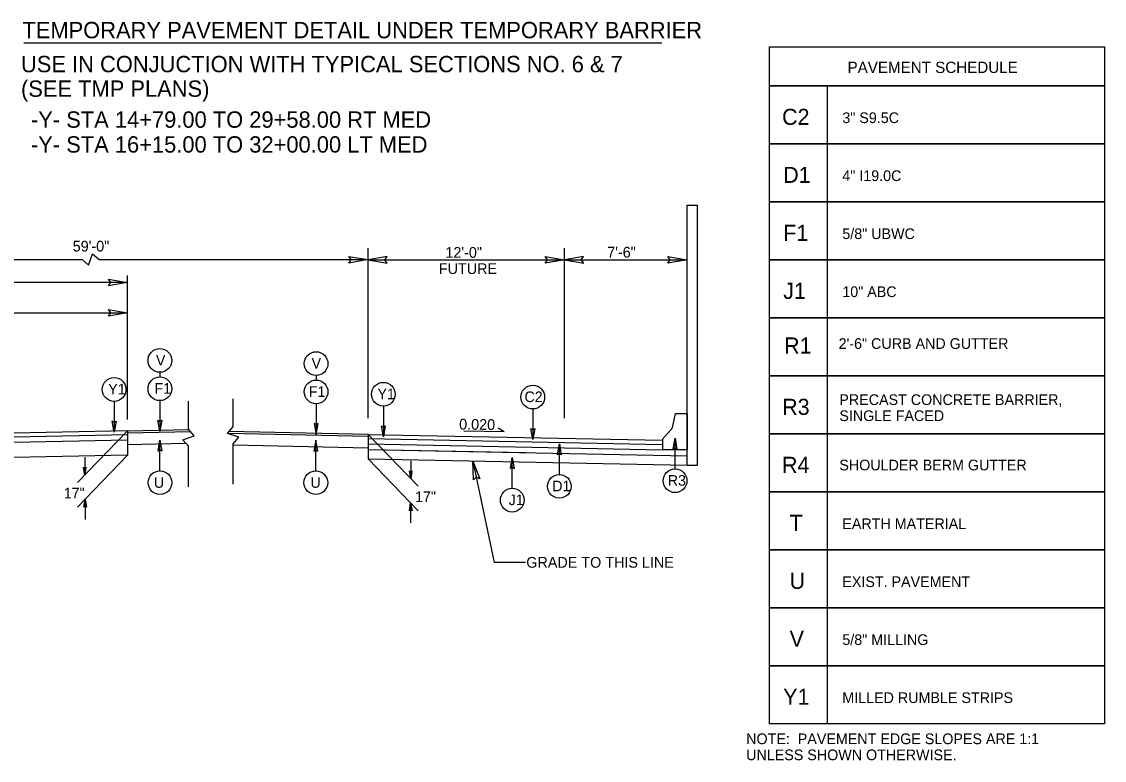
# Model space of a CAD drawing. Extents: x 1901582 to 1902252, y 193723 to 194156.
# Drawn here: x 1902064.9 to 1902131, y 193832.2 to 193877.4 of the extents above; entities that cross this region are included whole.
import ezdxf

# ---------------------------------------------------------------- set-up
doc = ezdxf.new("R2010")
doc.units = 0
for name, color, linetype in [('Old_Level_1', 7, 'Continuous'), ('Old_Level_11', 7, 'Continuous'), ('Old_Level_2', 7, 'Continuous'), ('Old_Level_20', 7, 'Continuous'), ('Old_Level_21', 7, 'Continuous'), ('Prop Dimension', 7, 'Continuous'), ('Prop Dimension Text', 7, 'Continuous'), ('Prop Pavement Schedule Description CELL', 7, 'Continuous'), ('Prop Roadway Bridge', 7, 'Continuous'), ('Typical Bridge Rail CELL', 7, 'Continuous'), ('Typical Pavement Slope Information CELL', 7, 'Continuous'), ('Typical Terminator CELL', 7, 'Continuous'), ('Typical Text Asphalt at Bridge Approach CELL', 7, 'Continuous')]:
    doc.layers.add(name, color=color, linetype=linetype)

msp = doc.modelspace()

# ---------------------------------------------------------------- linework, layer by layer
at = {"layer": 'Old_Level_1'}
for p, q in [((1902071.36, 193852.371), (1902052.61, 193851.996)), ((1902071.36, 193852.371), (1902068.292, 193849.202)), ((1902071.36, 193852.371), (1902075.103, 193852.446)), ((1902071.36, 193852.371), (1902071.36, 193850.871)), ((1902071.36, 193852.245), (1902075.209, 193852.322)), ((1902086.05, 193852.15), (1902077.548, 193852.32)), ((1902086.05, 193852.15), (1902077.548, 193852.32)), ((1902071.36, 193851.788), (1902048.36, 193851.328)), ((1902071.36, 193852.121), (1902052.61, 193851.746)), ((1902071.36, 193851.538), (1902074.918, 193851.609)), ((1902086.05, 193852.024), (1902077.504, 193852.195)), ((1902086.05, 193852.15), (1902104.05, 193851.79)), ((1902086.05, 193852.15), (1902086.05, 193850.65)), ((1902086.05, 193852.15), (1902089.118, 193848.98)), ((1902086.05, 193851.317), (1902077.81, 193851.481)), ((1902086.05, 193851.233), (1902095.693, 193851.04)), ((1902086.05, 193851.233), (1902105.55, 193850.843)), ((1902071.36, 193850.871), (1902048.36, 193850.411)), ((1902071.36, 193850.871), (1902068.292, 193847.701)), ((1902068.741, 193850.754), (1902068.741, 193849.665)), ((1902086.05, 193850.65), (1902089.118, 193847.48)), ((1902086.05, 193850.65), (1902105.55, 193850.26)), ((1902088.669, 193850.532), (1902088.669, 193849.444)), ((1902092.458, 193850.522), (1902093.755, 193844.323)), ((1902068.741, 193849.665), (1902068.657, 193850.142)), ((1902068.741, 193849.665), (1902068.669, 193850.133)), ((1902068.681, 193850.124), (1902068.741, 193849.665)), ((1902068.741, 193849.665), (1902068.693, 193850.116)), ((1902068.705, 193850.107), (1902068.741, 193849.665)), ((1902068.741, 193849.665), (1902068.717, 193850.098)), ((1902068.729, 193850.089), (1902068.741, 193849.665)), ((1902068.741, 193849.665), (1902068.826, 193850.142)), ((1902068.814, 193850.133), (1902068.741, 193849.665)), ((1902068.741, 193849.665), (1902068.801, 193850.124)), ((1902068.789, 193850.116), (1902068.741, 193849.665)), ((1902068.741, 193849.665), (1902068.777, 193850.107)), ((1902068.765, 193850.098), (1902068.741, 193849.665)), ((1902068.741, 193849.665), (1902068.753, 193850.089)), ((1902068.741, 193850.08), (1902068.741, 193849.665)), ((1902088.669, 193849.444), (1902088.585, 193849.921)), ((1902088.596, 193849.912), (1902088.669, 193849.444)), ((1902088.669, 193849.444), (1902088.61, 193849.903)), ((1902088.622, 193849.895), (1902088.669, 193849.444)), ((1902088.669, 193849.444), (1902088.634, 193849.886)), ((1902088.645, 193849.877), (1902088.669, 193849.444)), ((1902088.669, 193849.444), (1902088.657, 193849.868)), ((1902088.669, 193849.444), (1902088.753, 193849.921)), ((1902088.669, 193849.444), (1902088.742, 193849.912)), ((1902088.73, 193849.903), (1902088.669, 193849.444)), ((1902088.669, 193849.444), (1902088.718, 193849.895)), ((1902088.705, 193849.886), (1902088.669, 193849.444)), ((1902088.669, 193849.444), (1902088.693, 193849.877)), ((1902088.681, 193849.868), (1902088.669, 193849.444)), ((1902088.669, 193849.859), (1902088.669, 193849.444)), ((1902068.758, 193848.182), (1902068.673, 193847.705)), ((1902068.685, 193847.714), (1902068.758, 193848.182)), ((1902068.758, 193848.182), (1902068.697, 193847.723)), ((1902068.709, 193847.732), (1902068.758, 193848.182)), ((1902068.758, 193848.182), (1902068.722, 193847.741)), ((1902068.734, 193847.749), (1902068.758, 193848.182)), ((1902068.758, 193848.182), (1902068.746, 193847.758)), ((1902068.758, 193848.182), (1902068.842, 193847.705)), ((1902068.769, 193847.758), (1902068.758, 193848.182)), ((1902068.758, 193848.182), (1902068.781, 193847.749)), ((1902068.793, 193847.741), (1902068.758, 193848.182)), ((1902068.758, 193848.182), (1902068.805, 193847.732)), ((1902068.817, 193847.723), (1902068.758, 193848.182)), ((1902068.758, 193848.182), (1902068.83, 193847.714)), ((1902068.758, 193848.182), (1902068.758, 193846.957)), ((1902088.653, 193847.961), (1902088.568, 193847.484)), ((1902088.653, 193847.961), (1902088.58, 193847.493)), ((1902088.593, 193847.502), (1902088.653, 193847.961)), ((1902088.653, 193847.961), (1902088.605, 193847.511)), ((1902088.617, 193847.519), (1902088.653, 193847.961)), ((1902088.653, 193847.961), (1902088.629, 193847.528)), ((1902088.641, 193847.537), (1902088.653, 193847.961)), ((1902088.653, 193847.961), (1902088.737, 193847.484)), ((1902088.725, 193847.493), (1902088.653, 193847.961)), ((1902088.653, 193847.961), (1902088.713, 193847.502)), ((1902088.701, 193847.511), (1902088.653, 193847.961)), ((1902088.653, 193847.961), (1902088.689, 193847.519)), ((1902088.677, 193847.528), (1902088.653, 193847.961)), ((1902088.653, 193847.961), (1902088.665, 193847.537)), ((1902088.653, 193847.961), (1902088.653, 193846.736)), ((1902095.664, 193844.323), (1902093.755, 193844.323))]:
    msp.add_line(p, q, dxfattribs=at)
at = {"layer": 'Old_Level_11'}
for p, q in [((1902065.016, 193876.08), (1902104.001, 193876.08)), ((1902073.331, 193855.942), (1902073.331, 193855.664)), ((1902082.874, 193855.749), (1902082.874, 193855.471)), ((1902073.331, 193854.213), (1902073.331, 193852.339)), ((1902070.533, 193854.169), (1902070.533, 193852.295)), ((1902082.874, 193854.02), (1902082.874, 193852.146)), ((1902086.987, 193853.877), (1902086.987, 193852.003)), ((1902096.117, 193853.704), (1902096.117, 193851.83)), ((1902073.334, 193849.925), (1902073.334, 193851.8)), ((1902082.859, 193849.923), (1902082.859, 193851.797)), ((1902097.742, 193849.701), (1902097.742, 193851.575)), ((1902104.812, 193850.043), (1902104.812, 193851.917)), ((1902094.864, 193848.856), (1902094.864, 193850.73))]:
    msp.add_line(p, q, dxfattribs=at)
for points in [[(1902070.648, 193852.966), (1902070.533, 193852.295), (1902070.413, 193852.97), (1902070.533, 193852.884)], [(1902073.446, 193853.011), (1902073.331, 193852.339), (1902073.211, 193853.014), (1902073.331, 193852.928)], [(1902082.759, 193852.818), (1902082.874, 193852.146), (1902082.994, 193852.821), (1902082.874, 193852.735)], [(1902087.103, 193852.674), (1902086.987, 193852.003), (1902086.868, 193852.678), (1902086.987, 193852.592)], [(1902096.233, 193852.502), (1902096.117, 193851.83), (1902095.998, 193852.505), (1902096.117, 193852.42)], [(1902073.218, 193851.128), (1902073.334, 193851.8), (1902073.453, 193851.124), (1902073.334, 193851.21)], [(1902082.975, 193851.126), (1902082.859, 193851.797), (1902082.74, 193851.122), (1902082.859, 193851.208)], [(1902097.626, 193850.903), (1902097.742, 193851.575), (1902097.861, 193850.9), (1902097.742, 193850.985)], [(1902104.696, 193851.246), (1902104.812, 193851.917), (1902104.931, 193851.242), (1902104.812, 193851.328)], [(1902094.749, 193850.059), (1902094.864, 193850.73), (1902094.984, 193850.055), (1902094.864, 193850.141)]]:
    msp.add_lwpolyline(points, close=True, dxfattribs=at)
for centre in [(1902073.331, 193856.667), (1902082.874, 193856.474), (1902070.533, 193854.894), (1902073.331, 193854.938), (1902082.874, 193854.745), (1902086.987, 193854.602), (1902096.117, 193854.43), (1902073.334, 193849.2), (1902082.859, 193849.198), (1902097.742, 193848.976), (1902104.812, 193849.318), (1902094.864, 193848.131)]:
    msp.add_circle(centre, 0.725, dxfattribs=at)
at = {"layer": 'Prop Dimension'}
for p, q in [((1902086.05, 193853.142), (1902086.05, 193863.53)), ((1902098.05, 193853.142), (1902098.05, 193863.53)), ((1902086.05, 193862.825), (1902098.05, 193862.825)), ((1902098.05, 193862.825), (1902105.55, 193862.825)), ((1902071.36, 193853.064), (1902071.36, 193861.864)), ((1902071.36, 193861.432), (1902025.36, 193861.432)), ((1902051.11, 193859.581), (1902071.36, 193859.581)), ((1902086.05, 193851.9), (1902104.05, 193851.54)), ((1902086.05, 193851.567), (1902104.05, 193851.207))]:
    msp.add_line(p, q, dxfattribs=at)
msp.add_lwpolyline([(1902048.36, 193862.826), (1902068.573, 193862.826), (1902068.97, 193862.485), (1902069.212, 193863.182), (1902069.625, 193862.827), (1902086.05, 193862.826)], dxfattribs=at)
at = {"layer": 'Prop Pavement Schedule Description CELL'}
msp.add_lwpolyline([(1902110.585, 193875.841), (1902131.047, 193875.841), (1902131.047, 193873.438), (1902110.585, 193873.438)], close=True, dxfattribs=at)
for points in [[(1902114.129, 193869.894), (1902110.585, 193869.894), (1902110.585, 193873.438), (1902131.047, 193873.438), (1902131.047, 193869.894), (1902114.129, 193869.894), (1902114.129, 193873.438)], [(1902114.129, 193866.351), (1902110.585, 193866.351), (1902110.585, 193869.894), (1902131.047, 193869.894), (1902131.047, 193866.351), (1902114.129, 193866.351), (1902114.129, 193869.894)], [(1902114.129, 193862.807), (1902110.585, 193862.807), (1902110.585, 193866.351), (1902131.047, 193866.351), (1902131.047, 193862.807), (1902114.129, 193862.807), (1902114.129, 193866.351)], [(1902114.129, 193859.263), (1902110.585, 193859.263), (1902110.585, 193862.807), (1902131.047, 193862.807), (1902131.047, 193859.263), (1902114.129, 193859.263), (1902114.129, 193862.807)], [(1902114.129, 193855.72), (1902110.585, 193855.72), (1902110.585, 193859.263), (1902131.047, 193859.263), (1902131.047, 193855.72), (1902114.129, 193855.72), (1902114.129, 193859.263)], [(1902114.129, 193852.176), (1902110.585, 193852.176), (1902110.585, 193855.72), (1902131.047, 193855.72), (1902131.047, 193852.176), (1902114.129, 193852.176), (1902114.129, 193855.72)], [(1902114.129, 193848.632), (1902110.585, 193848.632), (1902110.585, 193852.176), (1902131.047, 193852.176), (1902131.047, 193848.632), (1902114.129, 193848.632), (1902114.129, 193852.176)], [(1902114.129, 193845.089), (1902110.585, 193845.089), (1902110.585, 193848.632), (1902131.047, 193848.632), (1902131.047, 193845.089), (1902114.129, 193845.089), (1902114.129, 193848.632)], [(1902114.129, 193841.545), (1902110.585, 193841.545), (1902110.585, 193845.089), (1902131.047, 193845.089), (1902131.047, 193841.545), (1902114.129, 193841.545), (1902114.129, 193845.089)], [(1902114.129, 193838.001), (1902110.585, 193838.001), (1902110.585, 193841.545), (1902131.047, 193841.545), (1902131.047, 193838.001), (1902114.129, 193838.001), (1902114.129, 193841.545)], [(1902114.129, 193834.458), (1902110.585, 193834.458), (1902110.585, 193838.001), (1902131.047, 193838.001), (1902131.047, 193834.458), (1902114.129, 193834.458), (1902114.129, 193838.001)]]:
    msp.add_lwpolyline(points, dxfattribs=at)
at = {"layer": 'Prop Roadway Bridge'}
for p, q in [((1902105.55, 193850.26), (1902105.55, 193866.153)), ((1902105.55, 193866.153), (1902106.19, 193866.153)), ((1902106.19, 193850.26), (1902106.19, 193866.153)), ((1902105.55, 193850.26), (1902106.19, 193850.26))]:
    msp.add_line(p, q, dxfattribs=at)
at = {"layer": 'Typical Bridge Rail CELL'}
for p, q in [((1902104.681, 193852.657), (1902104.846, 193853.431)), ((1902104.846, 193853.431), (1902105.524, 193853.431)), ((1902105.524, 193853.431), (1902105.55, 193853.405)), ((1902105.55, 193853.405), (1902105.55, 193851.206)), ((1902104.05, 193851.859), (1902104.563, 193852.426)), ((1902104.05, 193851.859), (1902104.05, 193851.206)), ((1902105.55, 193851.206), (1902104.05, 193851.207))]:
    msp.add_line(p, q, dxfattribs=at)
msp.add_arc((1902104.192, 193852.761), 0.5, 317.86989, 348.00424, dxfattribs=at)
at = {"layer": 'Typical Pavement Slope Information CELL'}
for q in [(1902091.901, 193852.352), (1902093.995, 193852.529)]:
    msp.add_line((1902094.371, 193852.302), q, dxfattribs=at)
at = {"layer": 'Typical Terminator CELL'}
for points in [[(1902084.878, 193863.028), (1902086.05, 193862.826), (1902084.872, 193862.618), (1902085.021, 193862.826)], [(1902087.222, 193863.027), (1902086.05, 193862.825), (1902087.228, 193862.617), (1902087.078, 193862.825)], [(1902096.878, 193863.027), (1902098.05, 193862.825), (1902096.872, 193862.617), (1902097.021, 193862.825)], [(1902099.222, 193863.027), (1902098.05, 193862.825), (1902099.228, 193862.617), (1902099.078, 193862.825)], [(1902104.378, 193863.027), (1902105.55, 193862.825), (1902104.372, 193862.617), (1902104.521, 193862.825)], [(1902070.188, 193861.634), (1902071.36, 193861.432), (1902070.182, 193861.224), (1902070.332, 193861.432)], [(1902070.188, 193859.783), (1902071.36, 193859.581), (1902070.182, 193859.373), (1902070.332, 193859.581)], [(1902092.5, 193849.366), (1902092.458, 193850.522), (1902092.892, 193849.441), (1902092.663, 193849.542)]]:
    msp.add_lwpolyline(points, close=True, dxfattribs=at)
at = {"layer": 'Typical Text Asphalt at Bridge Approach CELL'}
for points in [[(1902077.81, 193849.098), (1902077.81, 193851.573), (1902078.152, 193851.97), (1902077.455, 193852.212), (1902077.81, 193852.625), (1902077.814, 193854.327)], [(1902075.079, 193848.947), (1902075.079, 193851.422), (1902074.737, 193851.819), (1902075.433, 193852.061), (1902075.079, 193852.474), (1902075.075, 193854.176)]]:
    msp.add_lwpolyline(points, dxfattribs=at)

# ---------------------------------------------------------------- texts
at = {"layer": 'Old_Level_1'}
for s, p in [('59\'-0"', (1902068.002, 193863.322)), ('12\'-0"', (1902090.778, 193862.939)), ('7\'-6"', (1902100.666, 193862.955)), ('GRADE TO THIS LINE', (1902095.722, 193844.003))]:
    msp.add_text(s, height=0.656, dxfattribs=at).set_placement(p)
at = {"layer": 'Old_Level_11'}
for s, p in [('TEMPORARY PAVEMENT DETAIL UNDER TEMPORARY BARRIER', (1902064.93, 193876.354)), ('USE IN CONJUCTION WITH TYPICAL SECTIONS NO. 6 & 7', (1902064.841, 193874.277)), ('(SEE TMP PLANS)', (1902064.841, 193872.777)), ('-Y- STA 14+79.00 TO 29+58.00 RT MED', (1902065.45, 193870.887)), ('-Y- STA 16+15.00 TO 32+00.00 LT MED', (1902065.45, 193869.367))]:
    msp.add_text(s, height=1, dxfattribs=at).set_placement(p)
at = {"layer": 'Old_Level_2'}
msp.add_text('0.020', height=0.656, rotation=359.20147, dxfattribs=at).set_placement((1902091.615, 193852.448))
at = {"layer": 'Old_Level_20'}
for s, height, p in [('V', 0.649, (1902073.088, 193856.361)), ('V', 0.649, (1902082.601, 193856.168)), ('Y1', 0.6491, (1902070.172, 193854.588)), ('F1', 0.6491, (1902072.999, 193854.632)), ('F1', 0.6491, (1902082.433, 193854.439)), ('Y1', 0.6491, (1902086.627, 193854.296)), ('C2', 0.6491, (1902095.611, 193854.123)), ('R3', 0.6491, (1902104.367, 193849.014)), ('U', 0.649, (1902072.962, 193848.886)), ('U', 0.649, (1902082.531, 193848.883)), ('D1', 0.6491, (1902097.309, 193848.672)), ('17"', 0.6491, (1902067.455, 193848.24)), ('17"', 0.6491, (1902088.926, 193848.018)), ('J1', 0.6491, (1902094.646, 193847.827))]:
    msp.add_text(s, height=height, dxfattribs=at).set_placement(p)
at = {"layer": 'Old_Level_21'}
for s, height, p in [('C2', 0.98, (1902111.353, 193871.062)), ('3" S9.5C', 0.653, (1902115.034, 193871.172)), ('D1', 0.98, (1902111.423, 193867.518)), ('4" I19.0C', 0.653, (1902115.034, 193867.629)), ('F1', 0.98, (1902111.423, 193863.975)), ('5/8" UBWC', 0.653, (1902115.034, 193864.085)), ('J1', 0.98, (1902111.423, 193860.431)), ('10" ABC', 0.653, (1902115.034, 193860.541)), ('R1', 0.98, (1902111.475, 193857.091)), ('2\'-6" CURB AND GUTTER', 0.653, (1902114.81, 193857.373)), ('R3', 0.98, (1902111.359, 193853.344)), ('PRECAST CONCRETE BARRIER, ', 0.653, (1902114.852, 193853.945)), ('SINGLE FACED', 0.653, (1902114.852, 193852.965)), ('R4', 0.98, (1902111.349, 193849.8)), ('SHOULDER BERM GUTTER', 0.653, (1902114.852, 193849.951)), ('T', 0.98, (1902111.811, 193846.256)), ('EARTH MATERIAL', 0.653, (1902115.034, 193846.366)), ('U', 0.98, (1902111.811, 193842.712)), ('EXIST. PAVEMENT', 0.653, (1902115.034, 193842.823)), ('V', 0.98, (1902111.815, 193839.169)), ('5/8" MILLING', 0.653, (1902115.034, 193839.279)), ('Y1', 0.98, (1902111.423, 193835.625)), ('MILLED RUMBLE STRIPS', 0.653, (1902115.034, 193835.735)), ('NOTE:  PAVEMENT EDGE SLOPES ARE 1:1', 0.653, (1902109.158, 193833.222)), ('UNLESS SHOWN OTHERWISE.', 0.653, (1902109.158, 193832.242))]:
    msp.add_text(s, height=height, dxfattribs=at).set_placement(p)
at = {"layer": 'Prop Dimension Text'}
msp.add_text('FUTURE', height=0.656, dxfattribs=at).set_placement((1902090.378, 193861.949))
at = {"layer": 'Prop Pavement Schedule Description CELL'}
msp.add_text('PAVEMENT SCHEDULE', height=0.69299, dxfattribs=at).set_placement((1902115.354, 193874.231))

doc.saveas('drawing.dxf')
